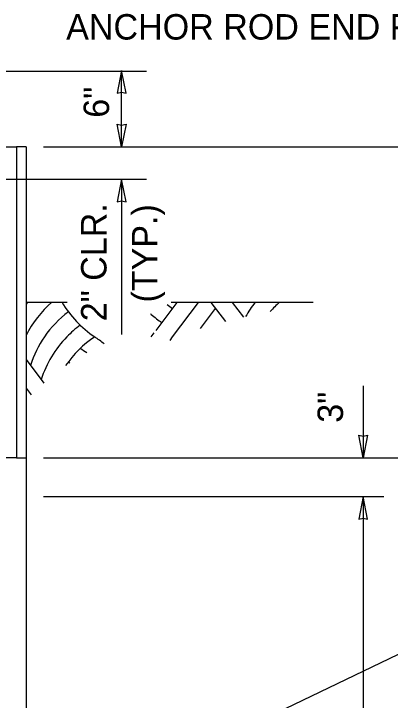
# Model space of a CAD drawing. Extents: x 99862 to 104211, y 98939 to 105076.
# Drawn here: x 102314.8 to 102551.3, y 101025.7 to 101457.3 of the extents above; entities that cross this region are included whole.
import ezdxf

# ---------------------------------------------------------------- set-up
doc = ezdxf.new("R2010")
doc.units = 0
for name, color, linetype in [('Level 15', 7, 'Continuous'), ('Level 2', 7, 'Continuous'), ('Level 20', 7, 'Continuous'), ('Level 9', 7, 'Continuous')]:
    doc.layers.add(name, color=color, linetype=linetype)

msp = doc.modelspace()

# ---------------------------------------------------------------- linework, layer by layer
at = {"layer": 'Level 15'}
for p, q in [((102147.89, 101421.14), (102398.21, 101421.14)), ((102382.59, 101373.58), (102382.59, 101421.14)), ((102333.46, 101373.58), (102639.27, 101373.58)), ((102239.01, 101353.23), (102398.21, 101353.23)), ((102382.59, 101353.23), (102382.59, 101255.64)), ((102534.31, 101223.32), (102534.31, 101178.16)), ((102333.46, 101178.16), (102594.03, 101178.16)), ((102333.46, 101153.73), (102547.34, 101153.73)), ((102534.31, 101153.73), (102534.31, 100429.01)), ((102387.34, 100973.37), (102660, 101104.51))]:
    msp.add_line(p, q, dxfattribs=at)
for points in [[(102382.59, 101421.55), (102379.8, 101407.32), (102382.59, 101407.98), (102385.38, 101407.32)], [(102382.59, 101373.58), (102379.8, 101387.81), (102382.59, 101387.15), (102385.38, 101387.81)], [(102382.59, 101353.23), (102379.8, 101339), (102382.59, 101339.66), (102385.38, 101339)], [(102534.31, 101178.16), (102531.52, 101192.38), (102534.31, 101191.72), (102537.1, 101192.38)], [(102534.31, 101153.73), (102531.52, 101139.5), (102534.31, 101140.16), (102537.1, 101139.5)]]:
    msp.add_lwpolyline(points, close=True, dxfattribs=at)
at = {"layer": 'Level 2'}
for p, q in [((101986.71, 101373.58), (102316.49, 101373.58)), ((102322.6, 101373.58), (102316.49, 101373.58)), ((102316.49, 101373.58), (102316.49, 101178.16)), ((102322.6, 101373.58), (102322.6, 101178.16)), ((102316.49, 101178.16), (101986.71, 101178.16)), ((102316.49, 101178.16), (102322.6, 101178.16)), ((102322.6, 101178.16), (102322.6, 100396.44))]:
    msp.add_line(p, q, dxfattribs=at)
at = {"layer": 'Level 9'}
for p, q in [((102348.32, 101275.87), (102322.6, 101275.87)), ((102322.6, 101275.73), (102322.97, 101275.24)), ((102404.19, 101258.19), (102417.45, 101275.87)), ((102502.86, 101275.87), (102413.71, 101275.87)), ((102414.61, 101254.18), (102430.89, 101275.87)), ((102429.98, 101275.87), (102430.45, 101275.24)), ((102438.65, 101275.87), (102447.74, 101263.75)), ((102452.08, 101275.87), (102459.07, 101266.56)), ((102432.04, 101259.5), (102441.48, 101272.09)), ((102401.18, 101254.18), (102403.07, 101256.69)), ((102412.97, 101251.98), (102414.61, 101254.18)), ((102322.6, 101239.91), (102333.67, 101225.15)), ((102322.6, 101221.99), (102325.84, 101217.67))]:
    msp.add_line(p, q, dxfattribs=at)
for centre, start, end in [((102383.41, 101224.61), 131.0747, 153.4267), ((102376.7, 101233.57), 141.528, 142.7093), ((102403.57, 101310.61), 210.7262, 236.0964), ((102452.54, 101328.53), 232.625, 236.0964), ((102519.72, 101233.57), 141.528, 150.6429), ((102526.44, 101224.61), 131.0747, 137.9344), ((102390.13, 101215.65), 127.1006, 145.4911), ((102445.83, 101319.57), 228.3537, 228.9599), ((102445.83, 101319.57), 228.9599, 236.0964), ((102396.85, 101206.7), 126.331, 135.7128), ((102390.13, 101215.65), 145.491, 162.3566), ((102396.85, 101206.7), 135.7127, 162.3566), ((102403.57, 101197.74), 123.9036, 145.6681), ((102327.71, 101197.74), 49.8065, 56.0963), ((102320.99, 101188.78), 54.3436, 58.5465), ((102314.27, 101179.83), 58.2729, 59.3021)]:
    msp.add_arc(centre, 68, start, end, dxfattribs=at)

# ---------------------------------------------------------------- texts
at = {"layer": 'Level 20'}
msp.add_text('ANCHOR ROD END FOR 1\' - 0" MIN.', height=16, dxfattribs=at).set_placement((102347.74, 101441.06))
for s, p in [('6"', (102374.68, 101391.92)), ('2" CLR.', (102373.08, 101263.97)), ('(TYP.)', (102405.08, 101275.75)), ('3"', (102521.65, 101200.17))]:
    msp.add_text(s, height=16, rotation=90, dxfattribs=at).set_placement(p)

doc.saveas('drawing.dxf')
